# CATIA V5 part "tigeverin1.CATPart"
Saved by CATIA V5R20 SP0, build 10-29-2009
Part number: tigeverin1
Bounding box of the stored display mesh (mm): x -260 to -50, y -210 to -190, z 17 to 37
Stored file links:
  D:\Dropbox\Pack 1 sylvain\mmoreau\mmoreau\mmoreau\fin\tigeverin1.CATPart
  U:\think motion\fin\think motion2.CATProduct
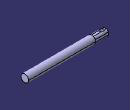
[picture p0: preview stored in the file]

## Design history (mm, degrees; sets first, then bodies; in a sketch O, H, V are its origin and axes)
External parameters (linked from other documents)
  `External.longueur tige verin2` = 200 mm
Set1
  Plane1: linked copy from another document
  Line1: linked copy from another document
  Point1: linked copy from another document
  Point2: linked copy from another document
Body1 (main body)
  Sketch1 on Plane1, origin (-50, 0, 0), H (0, 1, 0), V (0, 0, 1)
    line L1 (-208, 35) -> (-192, 35)
    line L2 (-192, 35) -> (-192, 19)
    line L3 (-192, 19) -> (-208, 19)
    line L4 (-208, 19) -> (-208, 35)
    reference projected point E1 (-200, 30) from Line1
    reference projected point E3 (-200, 30) from Point2
    distance L4 E1 = 8
    distance L2 L4 = 16 {= Sketch1.distance(L4 E1) *2}
    distance L3 L1 = 16 {= Sketch1.distance(L4 E1) *2}
    distance E3 L1 = 5
    horizontal: L1 H, L3 H
    vertical: L2 V, L4 V
  Pad1: profile Sketch1, direction (-1, 0, 0), length 210 {= `External.longueur tige verin2` +10mm}
  Sketch2 on face of Pad1 from Sketch1.L1, origin (-222.4087, -198.1964, 35), H (1, 0, 0), V (0, 1, 0)
    point P1 (-27.5913, -1.8036)
    reference projected point E1 (-27.5913, -1.8036) from Point2
    coincidence: E1 P1
  Hole1: placed by Sketch2, at (-250, -200, 35) direction (0, 0, -1), diameter 10, through (limit type 3)
  Fillet1: radius 5, on edge [face of Pad1 from Sketch1.L1 | face of Pad1 from Sketch1.L4]; edge [face of Pad1 from Sketch1.L2 | face of Pad1 from Sketch1.L1]; edge [face of Pad1 from Sketch1.L4 | face of Pad1 from Sketch1.L3]; edge [face of Pad1 from Sketch1.L3 | face of Pad1 from Sketch1.L2]
  Sketch3 on Plane1, origin (-50, 0, 0), H (0, 1, 0), V (0, 0, 1)
    circle A1 centre (-200, 27) radius 10
    point P1 (-200, 27)
    reference projected point E1 (-200, 30) from Line1
    reference projected point E2 (-200, 30) from Line1
    radius A1 = 10
    distance P1 E1 H = 0
    distance P1 E2 = 3
  Pad2: profile Sketch3, direction (-1, 0, 0), length 175
  Fillet2: radius 1, on edge [end face of Pad2 | face of Pad1 from Sketch1.L1]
